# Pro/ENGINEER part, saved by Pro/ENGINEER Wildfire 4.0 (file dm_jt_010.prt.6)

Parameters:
  METRIC = "NO"

Other parameters: PITCH, DRILL_POINT_ANGLE, DRILL_DEPTH, DRILL_DIAMETER, THREAD_DIAMETER, THREADS_PER_INCH, THREAD_DEPTH, THREAD_LENGTH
